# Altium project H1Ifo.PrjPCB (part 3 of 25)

## Sheet IfoPsl.SchDoc: D1800185
size C; Engineer: Daniel Sigg; DocumentNumber: 6; Revision: 4; SheetNumber: 6; SheetTotal: 8
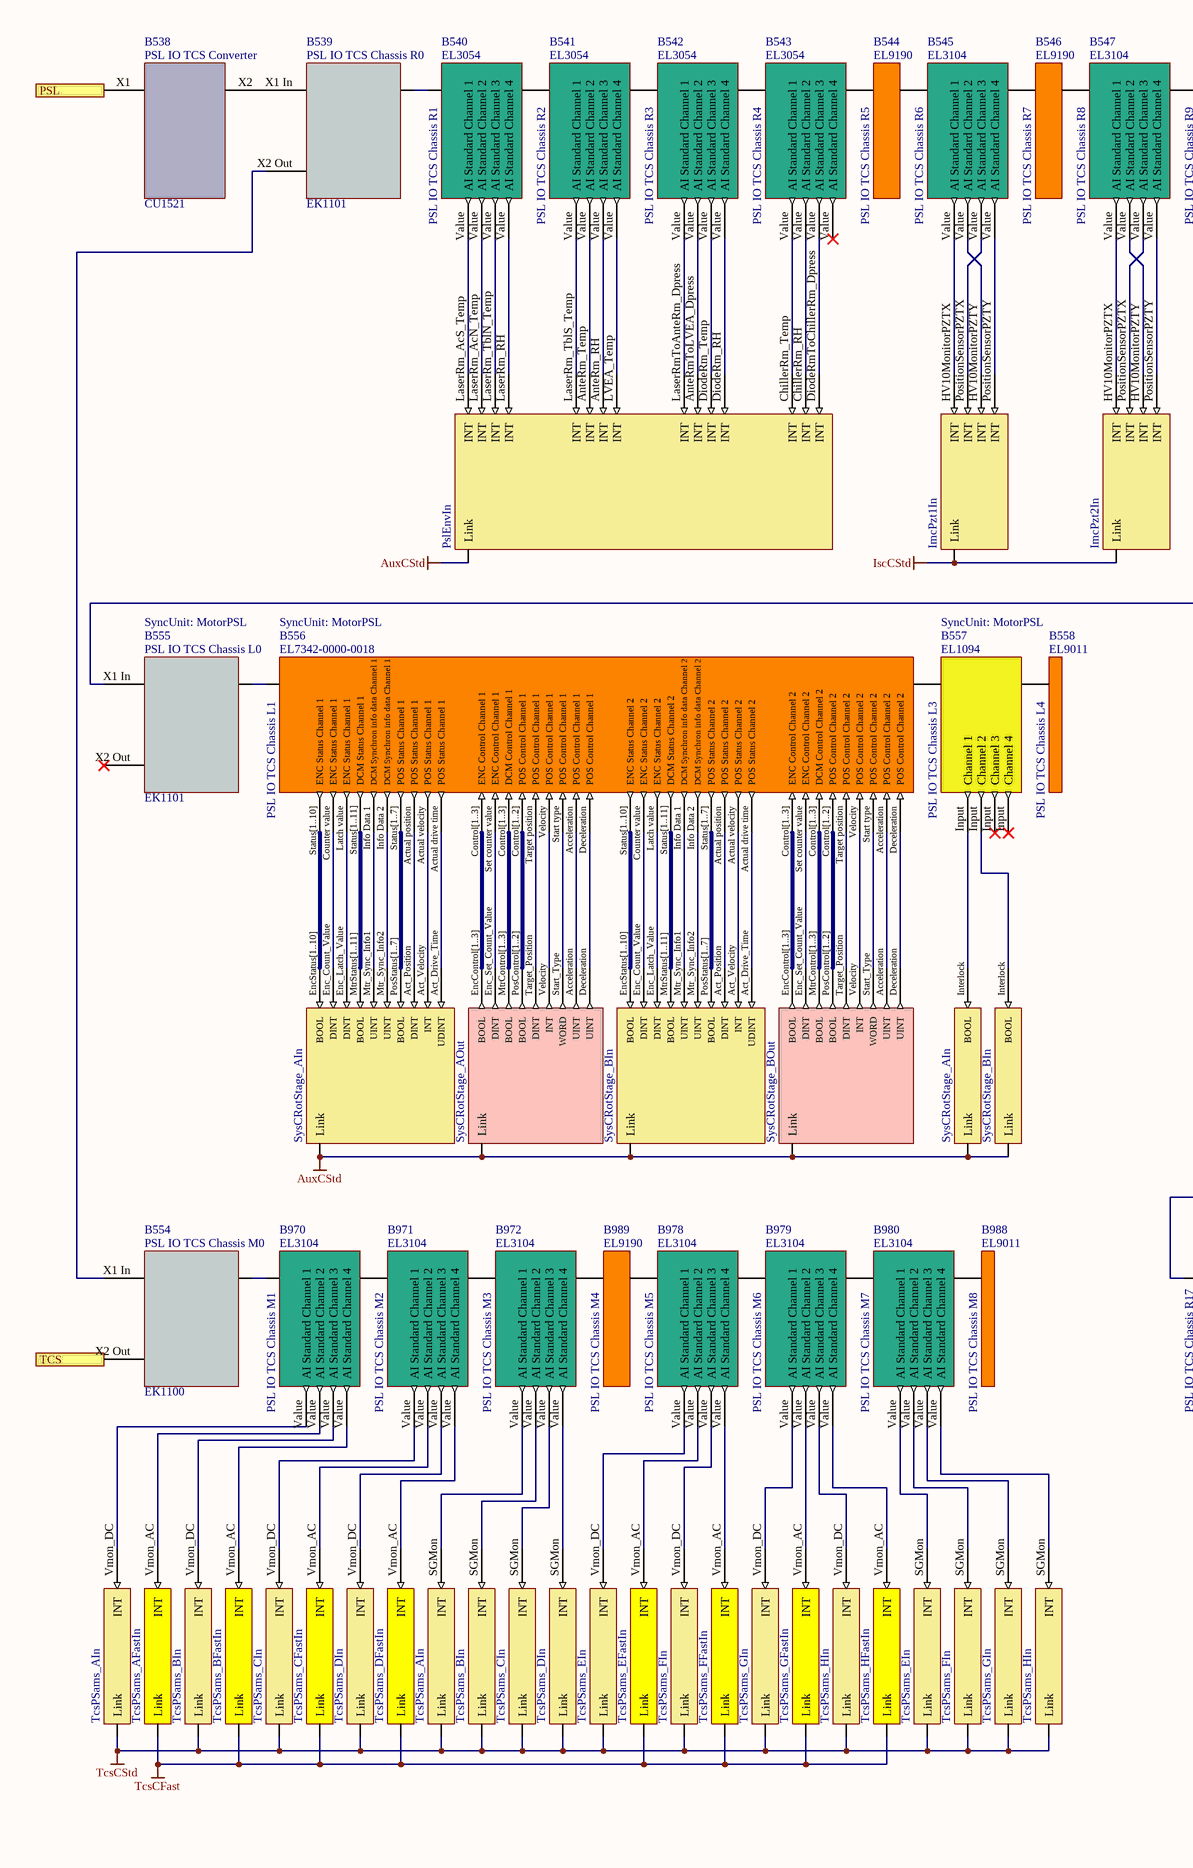
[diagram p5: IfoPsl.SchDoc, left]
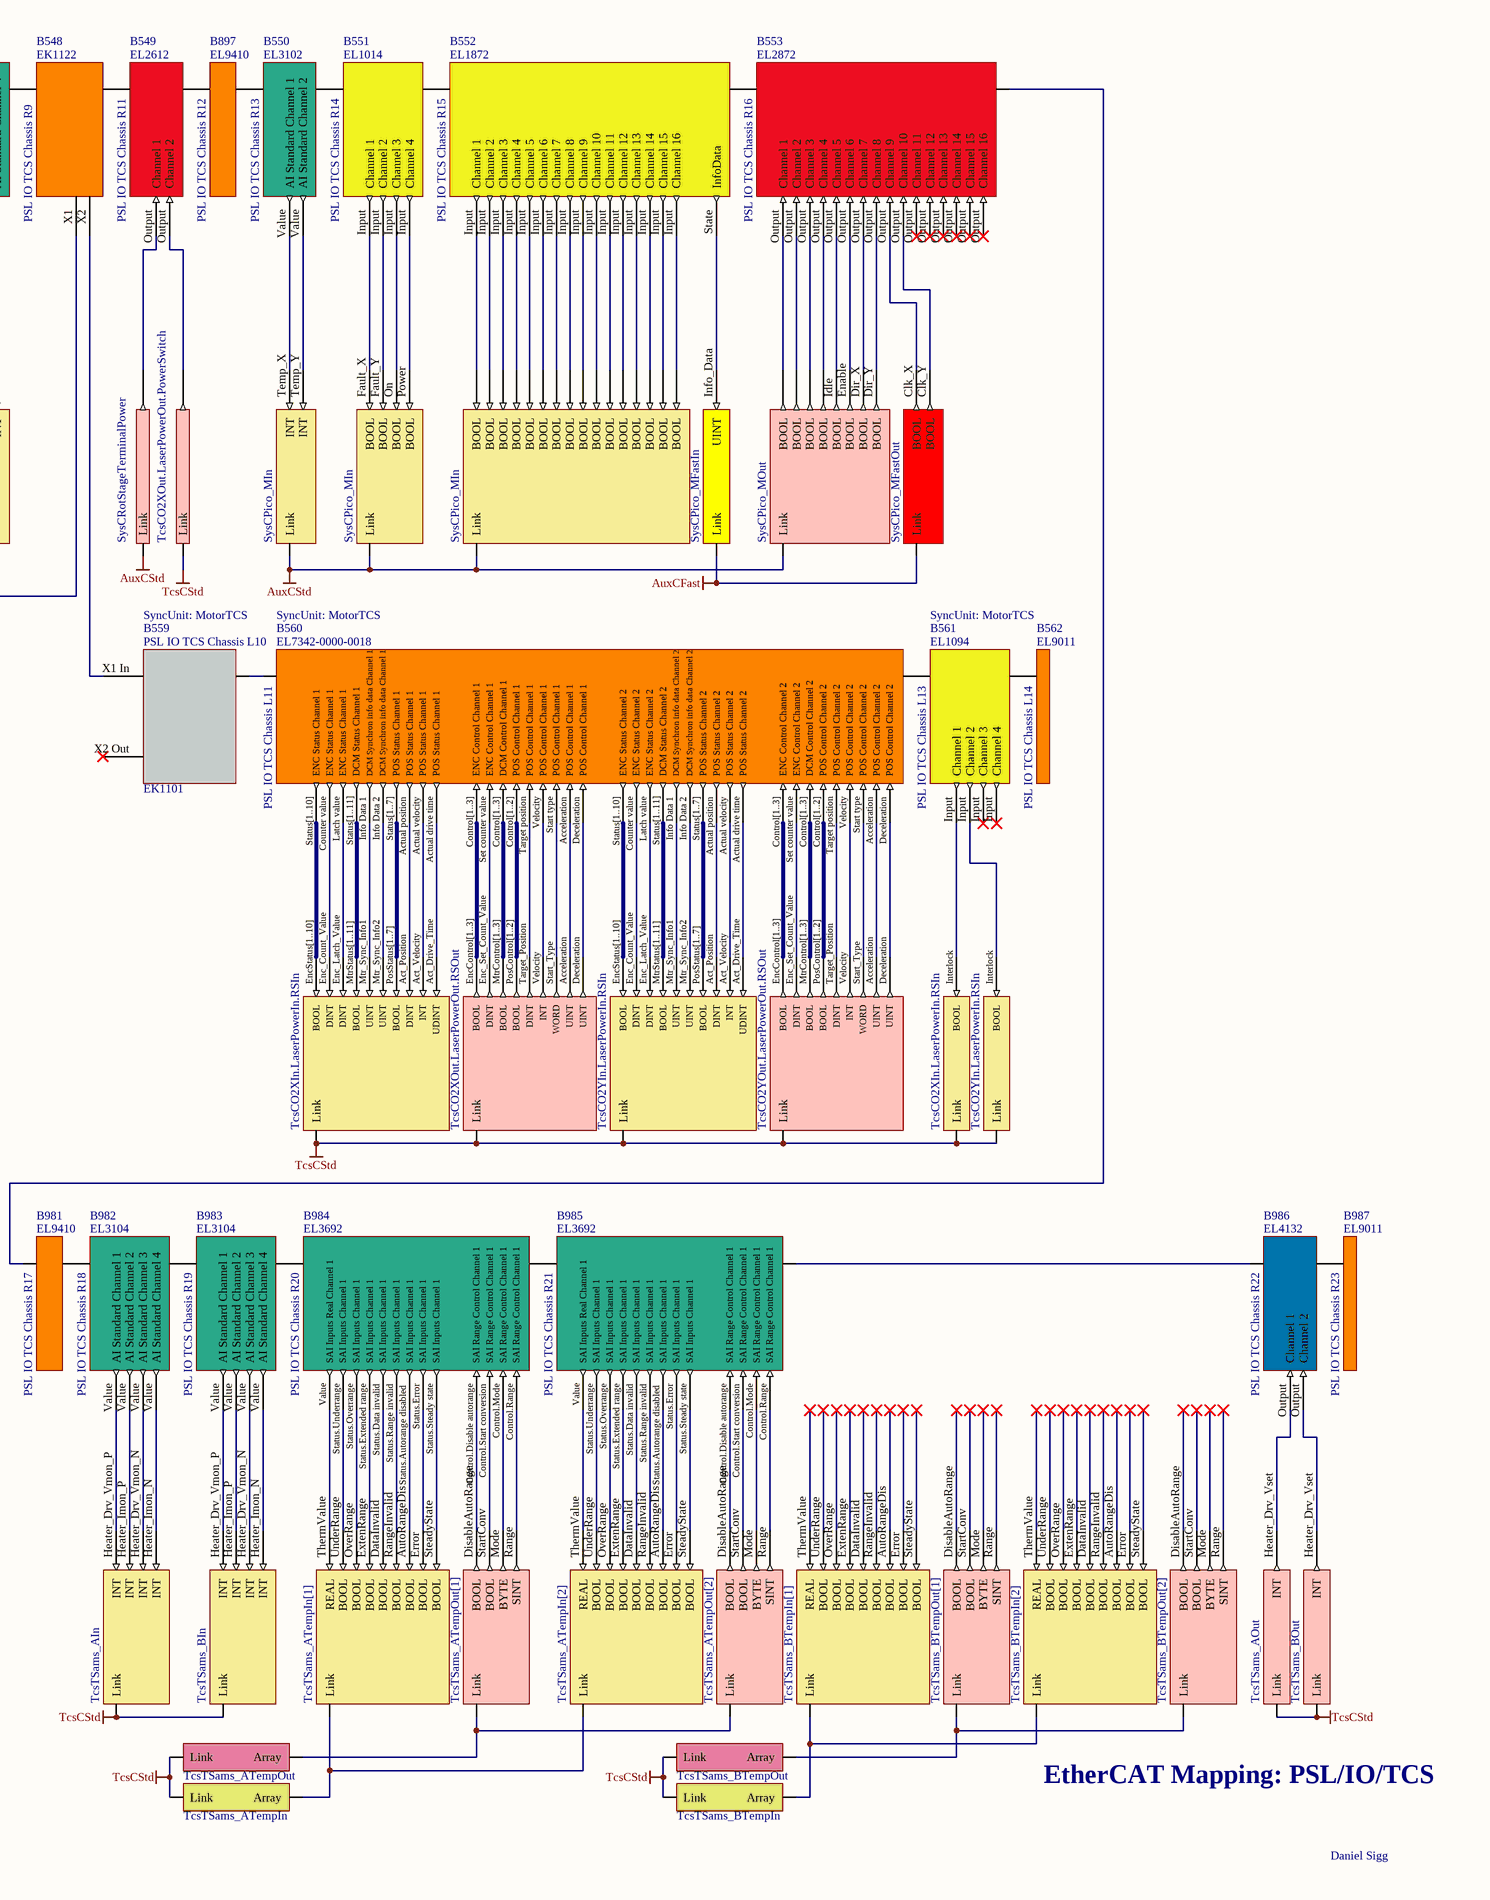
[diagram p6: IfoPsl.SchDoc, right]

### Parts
(Parts that share a designator on the sheet are numbered #1, #2 ... from top to bottom, then left to right.)
B538  PSL IO TCS Converter  Part Number: CU1521  (mechanical)
B539  PSL IO TCS Chassis R0  Part Number: EK1101  (mechanical)
B540  PSL IO TCS Chassis R1  Part Number: EL3054  (mechanical)
B541  PSL IO TCS Chassis R2  Part Number: EL3054  (mechanical)
B542  PSL IO TCS Chassis R3  Part Number: EL3054  (mechanical)
B543  PSL IO TCS Chassis R4  Part Number: EL3054  (mechanical)
B544  PSL IO TCS Chassis R5  Part Number: EL9190  (mechanical)
B545  PSL IO TCS Chassis R6  Part Number: EL3104  (mechanical)
B546  PSL IO TCS Chassis R7  Part Number: EL9190  (mechanical)
B547  PSL IO TCS Chassis R8  Part Number: EL3104  (mechanical)
B548  PSL IO TCS Chassis R9  Part Number: EK1122  (mechanical)
B549  PSL IO TCS Chassis R11  Part Number: EL2612  (mechanical)
B550  PSL IO TCS Chassis R13  Part Number: EL3102  (mechanical)
B551  PSL IO TCS Chassis R14  Part Number: EL1014  (mechanical)
B552  PSL IO TCS Chassis R15  Part Number: EL1872  (mechanical)
B553  PSL IO TCS Chassis R16  Part Number: EL2872  (mechanical)
B554  PSL IO TCS Chassis M0  Part Number: EK1100
B555  PSL IO TCS Chassis L0  Part Number: EK1101  SyncUnit: MotorPSL  (mechanical)
B556  PSL IO TCS Chassis L1  SyncUnit: MotorPSL  Part Number: EL7342-0000-0018  (mechanical)
B557  PSL IO TCS Chassis L3  Part Number: EL1094  SyncUnit: MotorPSL  (mechanical)
B558  PSL IO TCS Chassis L4  Part Number: EL9011  (mechanical)
B559  PSL IO TCS Chassis L10  Part Number: EK1101  SyncUnit: MotorTCS
B560  PSL IO TCS Chassis L11  SyncUnit: MotorTCS  Part Number: EL7342-0000-0018  (mechanical)
B561  PSL IO TCS Chassis L13  Part Number: EL1094  SyncUnit: MotorTCS  (mechanical)
B562  PSL IO TCS Chassis L14  Part Number: EL9011  (mechanical)
B897#1  PSL IO TCS Chassis R12  Part Number: EL9410  (mechanical)
B970  PSL IO TCS Chassis M1  Part Number: EL3104  (mechanical)
B971  PSL IO TCS Chassis M2  Part Number: EL3104  (mechanical)
B972  PSL IO TCS Chassis M3  Part Number: EL3104  (mechanical)
B978  PSL IO TCS Chassis M5  Part Number: EL3104  (mechanical)
B979  PSL IO TCS Chassis M6  Part Number: EL3104  (mechanical)
B980  PSL IO TCS Chassis M7  Part Number: EL3104  (mechanical)
B981  PSL IO TCS Chassis R17  Part Number: EL9410  (mechanical)
B982  PSL IO TCS Chassis R18  Part Number: EL3104  (mechanical)
B983  PSL IO TCS Chassis R19  Part Number: EL3104  (mechanical)
B984  PSL IO TCS Chassis R20  Part Number: EL3692  (mechanical)
B985  PSL IO TCS Chassis R21  Part Number: EL3692  (mechanical)
B986  PSL IO TCS Chassis R22  Part Number: EL4132  (mechanical)
B987  PSL IO TCS Chassis R23  Part Number: EL9011  (mechanical)
B988  PSL IO TCS Chassis M8  Part Number: EL9011  (mechanical)
B989  PSL IO TCS Chassis M4  Part Number: EL9190  (mechanical)
V423  SysCRotStage_AIn  (parts A,B of 2)  (no BOM)
V425  TcsCO2XIn.LaserPowerIn.RSIn  (parts A,B of 2)  (no BOM)
V427  TcsCO2YIn.LaserPowerIn.RSIn  (parts A,B of 2)  (no BOM)
V508  PslEnvIn  (no BOM)
V509  ImcPzt1In  (no BOM)
V510  ImcPzt2In  (no BOM)
V511  SysCRotStageTerminalPower  (no BOM)
V512  TcsCO2XOut.LaserPowerOut.PowerSwitch  (no BOM)
V513  SysCPico_MFastIn  (no BOM)
V514  SysCPico_MOut  (no BOM)
V515  SysCPico_MFastOut  (no BOM)
V516  SysCRotStage_AOut  (no BOM)
V517  TcsCO2XOut.LaserPowerOut.RSOut  (no BOM)
V518  TcsCO2YOut.LaserPowerOut.RSOut  (no BOM)
V699  SysCPico_MIn  (parts A,B,C of 3)  (no BOM)
V801  SysCRotStage_BIn  (parts A,B of 2)  (no BOM)
V802  SysCRotStage_BOut  (no BOM)
V803  TcsTSams_ATempIn[1]  (no BOM)
V804  TcsTSams_ATempOut[1]  (no BOM)
V805  TcsTSams_ATempIn[2]  (no BOM)
V806  TcsTSams_ATempOut[2]  (no BOM)
V807  TcsTSams_BTempIn[1]  (no BOM)
V808  TcsTSams_BTempOut[1]  (no BOM)
V809  TcsTSams_BTempIn[2]  (no BOM)
V810  TcsTSams_BTempOut[2]  (no BOM)
V811  TcsTSams_ATempOut  (no BOM)
V812  TcsTSams_BTempOut  (no BOM)
V813  TcsTSams_ATempIn  (no BOM)
V814  TcsTSams_BTempIn  (no BOM)
V815  TcsTSams_AIn  (no BOM)
V816  TcsTSams_BIn  (no BOM)
V817  TcsTSams_AOut  (no BOM)
V818  TcsTSams_BOut  (no BOM)
V819  TcsPSams_AIn  (parts A,B of 2)  (no BOM)
V820  TcsPSams_AFastIn  (no BOM)
V821  TcsPSams_BIn  (parts A,B of 2)  (no BOM)
V822  TcsPSams_BFastIn  (no BOM)
V823  TcsPSams_CIn  (parts A,B of 2)  (no BOM)
V824  TcsPSams_CFastIn  (no BOM)
V825  TcsPSams_DIn  (parts A,B of 2)  (no BOM)
V826  TcsPSams_DFastIn  (no BOM)
V831  TcsPSams_EIn  (parts A,B of 2)  (no BOM)
V832  TcsPSams_EFastIn  (no BOM)
V833  TcsPSams_FIn  (parts A,B of 2)  (no BOM)
V834  TcsPSams_FFastIn  (no BOM)
V835  TcsPSams_GIn  (parts A,B of 2)  (no BOM)
V836  TcsPSams_GFastIn  (no BOM)
V837  TcsPSams_HIn  (parts A,B of 2)  (no BOM)
V838  TcsPSams_HFastIn  (no BOM)

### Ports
PSL, TCS

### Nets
AuxCFast: V513.0(Link) V515.0(Link)
AuxCStd: V423.0(Link) V423.1(Link) V508.0(Link) V511.?2(Link) V514.0(Link) V516.0(Link) V699.0(Link) V699.1(Link) V699.2(Link) V801.0(Link) V801.1(Link) V802.0(Link)
IscCStd: V509.0(Link) V510.0(Link)
TcsCFast: V820.1(Link) V822.1(Link) V824.1(Link) V826.1(Link) V832.1(Link) V834.1(Link) V836.1(Link) V838.1(Link)
TcsCStd: V425.0(Link) V425.1(Link) V427.0(Link) V427.1(Link) V512.?2(Link) V517.0(Link) V518.0(Link) V811.?1(Link) V812.?1(Link) V813.?1(Link) V814.?1(Link) V815.1(Link) V816.1(Link) V817.0(Link) V818.0(Link) V819.1(Link) V819.2(Link) V821.1(Link) V821.2(Link) V823.1(Link) V823.2(Link) V825.1(Link) V825.2(Link) V831.1(Link) V831.2(Link) V833.1(Link) V833.2(Link) V835.1(Link) V835.2(Link) V837.1(Link) V837.2(Link)
NetB538_X1: B538.X1(A) ; port PSL
NetB538_X2: B538.X2(B) B539.X1_In(A)
NetB539_Ebus: B539.Ebus(B) B540.Ebus(A)
NetB539_X2 Out: B539.X2_Out(C) B554.X1_In(A)
NetB540_Ebus: B540.Ebus(B) B541.Ebus(A)
NetB540_Value: B540.Value(AI_Standard_Channel_1) V508.LaserRm_AcS_Temp(INT)
NetB540_Value: B540.Value(AI_Standard_Channel_2) V508.LaserRm_AcN_Temp(INT)  [a separate net that carries the same name]
NetB540_Value: B540.Value(AI_Standard_Channel_3) V508.LaserRm_TblN_Temp(INT)  [a separate net that carries the same name]
NetB540_Value: B540.Value(AI_Standard_Channel_4) V508.LaserRm_RH(INT)  [a separate net that carries the same name]
NetB541_Ebus: B541.Ebus(B) B542.Ebus(A)
NetB541_Value: B541.Value(AI_Standard_Channel_1) V508.LaserRm_TblS_Temp(INT)
NetB541_Value: B541.Value(AI_Standard_Channel_2) V508.AnteRm_Temp(INT)  [a separate net that carries the same name]
NetB541_Value: B541.Value(AI_Standard_Channel_3) V508.AnteRm_RH(INT)  [a separate net that carries the same name]
NetB541_Value: B541.Value(AI_Standard_Channel_4) V508.LVEA_Temp(INT)  [a separate net that carries the same name]
NetB542_Ebus: B542.Ebus(B) B543.Ebus(A)
NetB542_Value: B542.Value(AI_Standard_Channel_1) V508.LaserRmToAnteRm_Dpress(INT)
NetB542_Value: B542.Value(AI_Standard_Channel_2) V508.AnteRmToLVEA_Dpress(INT)  [a separate net that carries the same name]
NetB542_Value: B542.Value(AI_Standard_Channel_3) V508.DiodeRm_Temp(INT)  [a separate net that carries the same name]
NetB542_Value: B542.Value(AI_Standard_Channel_4) V508.DiodeRm_RH(INT)  [a separate net that carries the same name]
NetB543_Ebus: B543.Ebus(B) B544.Ebus(A)
NetB543_Value: B543.Value(AI_Standard_Channel_1) V508.ChillerRm_Temp(INT)
NetB543_Value: B543.Value(AI_Standard_Channel_2) V508.ChillerRm_RH(INT)  [a separate net that carries the same name]
NetB543_Value: B543.Value(AI_Standard_Channel_3) V508.DiodeRmToChillerRm_Dpress(INT)  [a separate net that carries the same name]
NetB544_Ebus: B544.Ebus(B) B545.Ebus(A)
NetB545_Ebus: B545.Ebus(B) B546.Ebus(A)
NetB545_Value: B545.Value(AI_Standard_Channel_1) V509.HV10MonitorPZTX(INT)
NetB545_Value: B545.Value(AI_Standard_Channel_2) V509.HV10MonitorPZTY(INT)  [a separate net that carries the same name]
NetB545_Value: B545.Value(AI_Standard_Channel_3) V509.PositionSensorPZTX(INT)  [a separate net that carries the same name]
NetB545_Value: B545.Value(AI_Standard_Channel_4) V509.PositionSensorPZTY(INT)  [a separate net that carries the same name]
NetB546_Ebus: B546.Ebus(B) B547.Ebus(A)
NetB547_Ebus: B547.Ebus(B) B548.Ebus(A)
NetB547_Value: B547.Value(AI_Standard_Channel_1) V510.HV10MonitorPZTX(INT)
NetB547_Value: B547.Value(AI_Standard_Channel_2) V510.HV10MonitorPZTY(INT)  [a separate net that carries the same name]
NetB547_Value: B547.Value(AI_Standard_Channel_3) V510.PositionSensorPZTX(INT)  [a separate net that carries the same name]
NetB547_Value: B547.Value(AI_Standard_Channel_4) V510.PositionSensorPZTY(INT)  [a separate net that carries the same name]
NetB548_Ebus: B548.Ebus(C) B549.Ebus(A)
NetB548_X1: B548.X1(D) B555.X1_In(A)
NetB548_X2: B548.X2(B) B559.X1_In(A)
NetB549_Ebus: B549.Ebus(B) B897#1.Ebus(A)
NetB549_Output: B549.Output(Channel_1) V511.?1
NetB549_Output: B549.Output(Channel_2) V512.?1  [a separate net that carries the same name]
NetB550_Ebus: B550.Ebus(B) B551.Ebus(A)
NetB550_Ebus: B550.Ebus(A) B897#1.Ebus(B)  [a separate net that carries the same name]
NetB550_Value: B550.Value(AI_Standard_Channel_1) V699.Temp_X(INT)
NetB550_Value: B550.Value(AI_Standard_Channel_2) V699.Temp_Y(INT)  [a separate net that carries the same name]
NetB551_Ebus: B551.Ebus(B) B552.Ebus(A)
NetB551_Input: B551.Input(Channel_1) V699.Fault_X(BOOL)
NetB551_Input: B551.Input(Channel_2) V699.Fault_Y(BOOL)  [a separate net that carries the same name]
NetB551_Input: B551.Input(Channel_3) V699.On(BOOL)  [a separate net that carries the same name]
NetB551_Input: B551.Input(Channel_4) V699.Power(BOOL)  [a separate net that carries the same name]
NetB552_Ebus: B552.Ebus(B) B553.Ebus(A)
NetB552_Input: B552.Input(Channel_1) V699.MotorX1(BOOL)
NetB552_Input: B552.Input(Channel_2) V699.MotorX2(BOOL)  [a separate net that carries the same name]
NetB552_Input: B552.Input(Channel_3) V699.MotorX3(BOOL)  [a separate net that carries the same name]
NetB552_Input: B552.Input(Channel_4) V699.MotorX4(BOOL)  [a separate net that carries the same name]
NetB552_Input: B552.Input(Channel_5) V699.MotorX5(BOOL)  [a separate net that carries the same name]
NetB552_Input: B552.Input(Channel_6) V699.MotorX6(BOOL)  [a separate net that carries the same name]
NetB552_Input: B552.Input(Channel_7) V699.MotorX7(BOOL)  [a separate net that carries the same name]
NetB552_Input: B552.Input(Channel_8) V699.MotorX8(BOOL)  [a separate net that carries the same name]
NetB552_Input: B552.Input(Channel_9) V699.MotorY1(BOOL)  [a separate net that carries the same name]
NetB552_Input: B552.Input(Channel_10) V699.MotorY2(BOOL)  [a separate net that carries the same name]
NetB552_Input: B552.Input(Channel_11) V699.MotorY3(BOOL)  [a separate net that carries the same name]
NetB552_Input: B552.Input(Channel_12) V699.MotorY4(BOOL)  [a separate net that carries the same name]
NetB552_Input: B552.Input(Channel_13) V699.MotorY5(BOOL)  [a separate net that carries the same name]
NetB552_Input: B552.Input(Channel_14) V699.MotorY6(BOOL)  [a separate net that carries the same name]
NetB552_Input: B552.Input(Channel_15) V699.MotorY7(BOOL)  [a separate net that carries the same name]
NetB552_Input: B552.Input(Channel_16) V699.MotorY8(BOOL)  [a separate net that carries the same name]
NetB552_State: B552.State(InfoData) V513.Info_Data(UINT)
NetB553_Ebus: B553.Ebus(B) B981.Ebus(A)
NetB553_Output: B553.Output(Channel_1) V514.MOTOR3(BOOL)
NetB553_Output: B553.Output(Channel_2) V514.MOTOR2(BOOL)  [a separate net that carries the same name]
NetB553_Output: B553.Output(Channel_3) V514.MOTOR1(BOOL)  [a separate net that carries the same name]
NetB553_Output: B553.Output(Channel_4) V514.MOTOR4(BOOL)  [a separate net that carries the same name]
NetB553_Output: B553.Output(Channel_5) V514.Idle(BOOL)  [a separate net that carries the same name]
NetB553_Output: B553.Output(Channel_6) V514.Enable(BOOL)  [a separate net that carries the same name]
NetB553_Output: B553.Output(Channel_7) V514.Dir_X(BOOL)  [a separate net that carries the same name]
NetB553_Output: B553.Output(Channel_8) V514.Dir_Y(BOOL)  [a separate net that carries the same name]
NetB553_Output: B553.Output(Channel_9) V515.Clk_X(BOOL)  [a separate net that carries the same name]
NetB553_Output: B553.Output(Channel_10) V515.Clk_Y(BOOL)  [a separate net that carries the same name]
NetB554_Ebus: B554.Ebus(B) B970.Ebus(A)
NetB554_X2 Out: B554.X2_Out(C) ; port TCS
NetB555_Ebus: B555.Ebus(B) B556.Ebus(A)
NetB556_Acceleration: B556.Acceleration(POS_Control_Channel_1) V516.Acceleration(UINT)
NetB556_Acceleration: B556.Acceleration(POS_Control_Channel_2) V802.Acceleration(UINT)  [a separate net that carries the same name]
NetB556_Actual drive time: B556.Actual_drive_time(POS_Status_Channel_1) V423.Act_Drive_Time(UDINT)
NetB556_Actual drive time: B556.Actual_drive_time(POS_Status_Channel_2) V801.Act_Drive_Time(UDINT)  [a separate net that carries the same name]
NetB556_Actual position: B556.Actual_position(POS_Status_Channel_1) V423.Act_Position(DINT)
NetB556_Actual position: B556.Actual_position(POS_Status_Channel_2) V801.Act_Position(DINT)  [a separate net that carries the same name]
NetB556_Actual velocity: B556.Actual_velocity(POS_Status_Channel_1) V423.Act_Velocity(INT)
NetB556_Actual velocity: B556.Actual_velocity(POS_Status_Channel_2) V801.Act_Velocity(INT)  [a separate net that carries the same name]
NetB556_Control[1..2]: B556.Control[1..2](POS_Control_Channel_1) V516.PosControl[1..2](BOOL)
NetB556_Control[1..2]: B556.Control[1..2](POS_Control_Channel_2) V802.PosControl[1..2](BOOL)  [a separate net that carries the same name]
NetB556_Control[1..3]: B556.Control[1..3](ENC_Control_Channel_1) V516.EncControl[1..3](BOOL)
NetB556_Control[1..3]: B556.Control[1..3](DCM_Control_Channel_1) V516.MtrControl[1..3](BOOL)  [a separate net that carries the same name]
NetB556_Control[1..3]: B556.Control[1..3](ENC_Control_Channel_2) V802.EncControl[1..3](BOOL)  [a separate net that carries the same name]
NetB556_Control[1..3]: B556.Control[1..3](DCM_Control_Channel_2) V802.MtrControl[1..3](BOOL)  [a separate net that carries the same name]
NetB556_Counter value: B556.Counter_value(ENC_Status_Channel_1) V423.Enc_Count_Value(DINT)
NetB556_Counter value: B556.Counter_value(ENC_Status_Channel_2) V801.Enc_Count_Value(DINT)  [a separate net that carries the same name]
NetB556_Deceleration: B556.Deceleration(POS_Control_Channel_1) V516.Deceleration(UINT)
NetB556_Deceleration: B556.Deceleration(POS_Control_Channel_2) V802.Deceleration(UINT)  [a separate net that carries the same name]
NetB556_Ebus: B556.Ebus(B) B557.Ebus(A)
NetB556_Info Data 1: B556.Info_Data_1(DCM_Synchron_info_data_Channel_1) V423.Mtr_Sync_Info1(UINT)
NetB556_Info Data 1: B556.Info_Data_1(DCM_Synchron_info_data_Channel_2) V801.Mtr_Sync_Info1(UINT)  [a separate net that carries the same name]
NetB556_Info Data 2: B556.Info_Data_2(DCM_Synchron_info_data_Channel_1) V423.Mtr_Sync_Info2(UINT)
NetB556_Info Data 2: B556.Info_Data_2(DCM_Synchron_info_data_Channel_2) V801.Mtr_Sync_Info2(UINT)  [a separate net that carries the same name]
NetB556_Latch value: B556.Latch_value(ENC_Status_Channel_1) V423.Enc_Latch_Value(DINT)
NetB556_Latch value: B556.Latch_value(ENC_Status_Channel_2) V801.Enc_Latch_Value(DINT)  [a separate net that carries the same name]
NetB556_Set counter value: B556.Set_counter_value(ENC_Control_Channel_1) V516.Enc_Set_Count_Value(DINT)
NetB556_Set counter value: B556.Set_counter_value(ENC_Control_Channel_2) V802.Enc_Set_Count_Value(DINT)  [a separate net that carries the same name]
NetB556_Start type: B556.Start_type(POS_Control_Channel_1) V516.Start_Type(WORD)
NetB556_Start type: B556.Start_type(POS_Control_Channel_2) V802.Start_Type(WORD)  [a separate net that carries the same name]
NetB556_Status[1..7]: B556.Status[1..7](POS_Status_Channel_1) V423.PosStatus[1..7](BOOL)
NetB556_Status[1..7]: B556.Status[1..7](POS_Status_Channel_2) V801.PosStatus[1..7](BOOL)  [a separate net that carries the same name]
NetB556_Status[1..10]: B556.Status[1..10](ENC_Status_Channel_1) V423.EncStatus[1..10](BOOL)
NetB556_Status[1..10]: B556.Status[1..10](ENC_Status_Channel_2) V801.EncStatus[1..10](BOOL)  [a separate net that carries the same name]
NetB556_Status[1..11]: B556.Status[1..11](DCM_Status_Channel_1) V423.MtrStatus[1..11](BOOL)
NetB556_Status[1..11]: B556.Status[1..11](DCM_Status_Channel_2) V801.MtrStatus[1..11](BOOL)  [a separate net that carries the same name]
NetB556_Target position: B556.Target_position(POS_Control_Channel_1) V516.Target_Position(DINT)
NetB556_Target position: B556.Target_position(POS_Control_Channel_2) V802.Target_Position(DINT)  [a separate net that carries the same name]
NetB556_Velocity: B556.Velocity(POS_Control_Channel_1) V516.Velocity(INT)
NetB556_Velocity: B556.Velocity(POS_Control_Channel_2) V802.Velocity(INT)  [a separate net that carries the same name]
NetB557_Ebus: B557.Ebus(B) B558.Ebus(A)
NetB557_Input: B557.Input(Channel_1) V423.Interlock(BOOL)
NetB557_Input: B557.Input(Channel_2) V801.Interlock(BOOL)  [a separate net that carries the same name]
NetB559_Ebus: B559.Ebus(B) B560.Ebus(A)
NetB560_Acceleration: B560.Acceleration(POS_Control_Channel_1) V517.Acceleration(UINT)
NetB560_Acceleration: B560.Acceleration(POS_Control_Channel_2) V518.Acceleration(UINT)  [a separate net that carries the same name]
NetB560_Actual drive time: B560.Actual_drive_time(POS_Status_Channel_1) V425.Act_Drive_Time(UDINT)
NetB560_Actual drive time: B560.Actual_drive_time(POS_Status_Channel_2) V427.Act_Drive_Time(UDINT)  [a separate net that carries the same name]
NetB560_Actual position: B560.Actual_position(POS_Status_Channel_1) V425.Act_Position(DINT)
NetB560_Actual position: B560.Actual_position(POS_Status_Channel_2) V427.Act_Position(DINT)  [a separate net that carries the same name]
NetB560_Actual velocity: B560.Actual_velocity(POS_Status_Channel_1) V425.Act_Velocity(INT)
NetB560_Actual velocity: B560.Actual_velocity(POS_Status_Channel_2) V427.Act_Velocity(INT)  [a separate net that carries the same name]
NetB560_Control[1..2]: B560.Control[1..2](POS_Control_Channel_1) V517.PosControl[1..2](BOOL)
NetB560_Control[1..2]: B560.Control[1..2](POS_Control_Channel_2) V518.PosControl[1..2](BOOL)  [a separate net that carries the same name]
NetB560_Control[1..3]: B560.Control[1..3](ENC_Control_Channel_1) V517.EncControl[1..3](BOOL)
NetB560_Control[1..3]: B560.Control[1..3](DCM_Control_Channel_1) V517.MtrControl[1..3](BOOL)  [a separate net that carries the same name]
NetB560_Control[1..3]: B560.Control[1..3](ENC_Control_Channel_2) V518.EncControl[1..3](BOOL)  [a separate net that carries the same name]
NetB560_Control[1..3]: B560.Control[1..3](DCM_Control_Channel_2) V518.MtrControl[1..3](BOOL)  [a separate net that carries the same name]
NetB560_Counter value: B560.Counter_value(ENC_Status_Channel_1) V425.Enc_Count_Value(DINT)
NetB560_Counter value: B560.Counter_value(ENC_Status_Channel_2) V427.Enc_Count_Value(DINT)  [a separate net that carries the same name]
NetB560_Deceleration: B560.Deceleration(POS_Control_Channel_1) V517.Deceleration(UINT)
NetB560_Deceleration: B560.Deceleration(POS_Control_Channel_2) V518.Deceleration(UINT)  [a separate net that carries the same name]
NetB560_Ebus: B560.Ebus(B) B561.Ebus(A)
NetB560_Info Data 1: B560.Info_Data_1(DCM_Synchron_info_data_Channel_1) V425.Mtr_Sync_Info1(UINT)
NetB560_Info Data 1: B560.Info_Data_1(DCM_Synchron_info_data_Channel_2) V427.Mtr_Sync_Info1(UINT)  [a separate net that carries the same name]
NetB560_Info Data 2: B560.Info_Data_2(DCM_Synchron_info_data_Channel_1) V425.Mtr_Sync_Info2(UINT)
NetB560_Info Data 2: B560.Info_Data_2(DCM_Synchron_info_data_Channel_2) V427.Mtr_Sync_Info2(UINT)  [a separate net that carries the same name]
NetB560_Latch value: B560.Latch_value(ENC_Status_Channel_1) V425.Enc_Latch_Value(DINT)
NetB560_Latch value: B560.Latch_value(ENC_Status_Channel_2) V427.Enc_Latch_Value(DINT)  [a separate net that carries the same name]
NetB560_Set counter value: B560.Set_counter_value(ENC_Control_Channel_1) V517.Enc_Set_Count_Value(DINT)
NetB560_Set counter value: B560.Set_counter_value(ENC_Control_Channel_2) V518.Enc_Set_Count_Value(DINT)  [a separate net that carries the same name]
NetB560_Start type: B560.Start_type(POS_Control_Channel_1) V517.Start_Type(WORD)
NetB560_Start type: B560.Start_type(POS_Control_Channel_2) V518.Start_Type(WORD)  [a separate net that carries the same name]
NetB560_Status[1..7]: B560.Status[1..7](POS_Status_Channel_1) V425.PosStatus[1..7](BOOL)
NetB560_Status[1..7]: B560.Status[1..7](POS_Status_Channel_2) V427.PosStatus[1..7](BOOL)  [a separate net that carries the same name]
NetB560_Status[1..10]: B560.Status[1..10](ENC_Status_Channel_1) V425.EncStatus[1..10](BOOL)
NetB560_Status[1..10]: B560.Status[1..10](ENC_Status_Channel_2) V427.EncStatus[1..10](BOOL)  [a separate net that carries the same name]
NetB560_Status[1..11]: B560.Status[1..11](DCM_Status_Channel_1) V425.MtrStatus[1..11](BOOL)
NetB560_Status[1..11]: B560.Status[1..11](DCM_Status_Channel_2) V427.MtrStatus[1..11](BOOL)  [a separate net that carries the same name]
NetB560_Target position: B560.Target_position(POS_Control_Channel_1) V517.Target_Position(DINT)
NetB560_Target position: B560.Target_position(POS_Control_Channel_2) V518.Target_Position(DINT)  [a separate net that carries the same name]
NetB560_Velocity: B560.Velocity(POS_Control_Channel_1) V517.Velocity(INT)
NetB560_Velocity: B560.Velocity(POS_Control_Channel_2) V518.Velocity(INT)  [a separate net that carries the same name]
NetB561_Ebus: B561.Ebus(B) B562.Ebus(A)
NetB561_Input: B561.Input(Channel_1) V425.Interlock(BOOL)
NetB561_Input: B561.Input(Channel_2) V427.Interlock(BOOL)  [a separate net that carries the same name]
NetB970_Ebus: B970.Ebus(B) B971.Ebus(A)
NetB970_Value: B970.Value(AI_Standard_Channel_1) V819.Vmon_DC(INT)
NetB970_Value: B970.Value(AI_Standard_Channel_2) V820.Vmon_AC(INT)  [a separate net that carries the same name]
NetB970_Value: B970.Value(AI_Standard_Channel_3) V821.Vmon_DC(INT)  [a separate net that carries the same name]
NetB970_Value: B970.Value(AI_Standard_Channel_4) V822.Vmon_AC(INT)  [a separate net that carries the same name]
NetB971_Ebus: B971.Ebus(B) B972.Ebus(A)
NetB971_Value: B971.Value(AI_Standard_Channel_1) V823.Vmon_DC(INT)
NetB971_Value: B971.Value(AI_Standard_Channel_2) V824.Vmon_AC(INT)  [a separate net that carries the same name]
NetB971_Value: B971.Value(AI_Standard_Channel_3) V825.Vmon_DC(INT)  [a separate net that carries the same name]
NetB971_Value: B971.Value(AI_Standard_Channel_4) V826.Vmon_AC(INT)  [a separate net that carries the same name]
NetB972_Ebus: B972.Ebus(B) B989.Ebus(A)
NetB972_Value: B972.Value(AI_Standard_Channel_1) V819.SGMon(INT)
NetB972_Value: B972.Value(AI_Standard_Channel_2) V821.SGMon(INT)  [a separate net that carries the same name]
NetB972_Value: B972.Value(AI_Standard_Channel_3) V823.SGMon(INT)  [a separate net that carries the same name]
NetB972_Value: B972.Value(AI_Standard_Channel_4) V825.SGMon(INT)  [a separate net that carries the same name]
NetB978_Ebus: B978.Ebus(A) B989.Ebus(B)
NetB978_Ebus: B978.Ebus(B) B979.Ebus(A)  [a separate net that carries the same name]
NetB978_Value: B978.Value(AI_Standard_Channel_1) V831.Vmon_DC(INT)
NetB978_Value: B978.Value(AI_Standard_Channel_2) V832.Vmon_AC(INT)  [a separate net that carries the same name]
NetB978_Value: B978.Value(AI_Standard_Channel_3) V833.Vmon_DC(INT)  [a separate net that carries the same name]
NetB978_Value: B978.Value(AI_Standard_Channel_4) V834.Vmon_AC(INT)  [a separate net that carries the same name]
NetB979_Ebus: B979.Ebus(B) B980.Ebus(A)
NetB979_Value: B979.Value(AI_Standard_Channel_1) V835.Vmon_DC(INT)
NetB979_Value: B979.Value(AI_Standard_Channel_2) V836.Vmon_AC(INT)  [a separate net that carries the same name]
NetB979_Value: B979.Value(AI_Standard_Channel_3) V837.Vmon_DC(INT)  [a separate net that carries the same name]
NetB979_Value: B979.Value(AI_Standard_Channel_4) V838.Vmon_AC(INT)  [a separate net that carries the same name]
NetB980_Ebus: B980.Ebus(B) B988.Ebus(A)
NetB980_Value: B980.Value(AI_Standard_Channel_1) V831.SGMon(INT)
NetB980_Value: B980.Value(AI_Standard_Channel_2) V833.SGMon(INT)  [a separate net that carries the same name]
NetB980_Value: B980.Value(AI_Standard_Channel_3) V835.SGMon(INT)  [a separate net that carries the same name]
NetB980_Value: B980.Value(AI_Standard_Channel_4) V837.SGMon(INT)  [a separate net that carries the same name]
NetB981_Ebus: B981.Ebus(B) B982.Ebus(A)
NetB982_Ebus: B982.Ebus(B) B983.Ebus(A)
NetB982_Value: B982.Value(AI_Standard_Channel_1) V815.Heater_Drv_Vmon_P(INT)
NetB982_Value: B982.Value(AI_Standard_Channel_2) V815.Heater_Imon_P(INT)  [a separate net that carries the same name]
NetB982_Value: B982.Value(AI_Standard_Channel_3) V815.Heater_Drv_Vmon_N(INT)  [a separate net that carries the same name]
NetB982_Value: B982.Value(AI_Standard_Channel_4) V815.Heater_Imon_N(INT)  [a separate net that carries the same name]
NetB983_Ebus: B983.Ebus(B) B984.Ebus(A)
NetB983_Value: B983.Value(AI_Standard_Channel_1) V816.Heater_Drv_Vmon_P(INT)
NetB983_Value: B983.Value(AI_Standard_Channel_2) V816.Heater_Imon_P(INT)  [a separate net that carries the same name]
NetB983_Value: B983.Value(AI_Standard_Channel_3) V816.Heater_Drv_Vmon_N(INT)  [a separate net that carries the same name]
NetB983_Value: B983.Value(AI_Standard_Channel_4) V816.Heater_Imon_N(INT)  [a separate net that carries the same name]
NetB984_Control.Disable autorange: B984.Control.Disable_autorange(SAI_Range_Control_Channel_1) V804.DisableAutoRange(BOOL)
NetB984_Control.Mode: B984.Control.Mode(SAI_Range_Control_Channel_1) V804.Mode(BYTE)
NetB984_Control.Range: B984.Control.Range(SAI_Range_Control_Channel_1) V804.Range(SINT)
NetB984_Control.Start conversion: B984.Control.Start_conversion(SAI_Range_Control_Channel_1) V804.StartConv(BOOL)
NetB984_Ebus: B984.Ebus(B) B985.Ebus(A)
NetB984_Status.Autorange disabled: B984.Status.Autorange_disabled(SAI_Inputs_Channel_1) V803.AutoRangeDis(BOOL)
NetB984_Status.Data invalid: B984.Status.Data_invalid(SAI_Inputs_Channel_1) V803.DataInvalid(BOOL)
NetB984_Status.Error: B984.Status.Error(SAI_Inputs_Channel_1) V803.Error(BOOL)
NetB984_Status.Extended range: B984.Status.Extended_range(SAI_Inputs_Channel_1) V803.ExtenRange(BOOL)
NetB984_Status.Overrange: B984.Status.Overrange(SAI_Inputs_Channel_1) V803.OverRange(BOOL)
NetB984_Status.Range invalid: B984.Status.Range_invalid(SAI_Inputs_Channel_1) V803.RangeInvalid(BOOL)
NetB984_Status.Steady state: B984.Status.Steady_state(SAI_Inputs_Channel_1) V803.SteadyState(BOOL)
NetB984_Status.Underrange: B984.Status.Underrange(SAI_Inputs_Channel_1) V803.UnderRange(BOOL)
NetB984_Value: B984.Value(SAI_Inputs_Real_Channel_1) V803.ThermValue(REAL)
NetB985_Control.Disable autorange: B985.Control.Disable_autorange(SAI_Range_Control_Channel_1) V806.DisableAutoRange(BOOL)
NetB985_Control.Mode: B985.Control.Mode(SAI_Range_Control_Channel_1) V806.Mode(BYTE)
NetB985_Control.Range: B985.Control.Range(SAI_Range_Control_Channel_1) V806.Range(SINT)
NetB985_Control.Start conversion: B985.Control.Start_conversion(SAI_Range_Control_Channel_1) V806.StartConv(BOOL)
NetB985_Ebus: B985.Ebus(B) B986.Ebus(A)
NetB985_Status.Autorange disabled: B985.Status.Autorange_disabled(SAI_Inputs_Channel_1) V805.AutoRangeDis(BOOL)
NetB985_Status.Data invalid: B985.Status.Data_invalid(SAI_Inputs_Channel_1) V805.DataInvalid(BOOL)
NetB985_Status.Error: B985.Status.Error(SAI_Inputs_Channel_1) V805.Error(BOOL)
NetB985_Status.Extended range: B985.Status.Extended_range(SAI_Inputs_Channel_1) V805.ExtenRange(BOOL)
NetB985_Status.Overrange: B985.Status.Overrange(SAI_Inputs_Channel_1) V805.OverRange(BOOL)
NetB985_Status.Range invalid: B985.Status.Range_invalid(SAI_Inputs_Channel_1) V805.RangeInvalid(BOOL)
NetB985_Status.Steady state: B985.Status.Steady_state(SAI_Inputs_Channel_1) V805.SteadyState(BOOL)
NetB985_Status.Underrange: B985.Status.Underrange(SAI_Inputs_Channel_1) V805.UnderRange(BOOL)
NetB985_Value: B985.Value(SAI_Inputs_Real_Channel_1) V805.ThermValue(REAL)
NetB986_Ebus: B986.Ebus(B) B987.Ebus(A)
NetB986_Output: B986.Output(Channel_1) V817.Heater_Drv_Vset(INT)
NetB986_Output: B986.Output(Channel_2) V818.Heater_Drv_Vset(INT)  [a separate net that carries the same name]
NetV803_1: V803.1(Link) V805.1(Link) V813.?2(Array)
NetV804_1: V804.1(Link) V806.1(Link) V811.?2(Array)
NetV807_1: V807.1(Link) V809.1(Link) V814.?2(Array)
NetV808_1: V808.1(Link) V810.1(Link) V812.?2(Array)

Not connected (* = marked no-connect by the designer): B555 X2 Out(C)*; B559 X2 Out(C)*; V807 AutoRangeDis(BOOL)* DataInvalid(BOOL)* Error(BOOL)* ExtenRange(BOOL)* OverRange(BOOL)* RangeInvalid(BOOL)* SteadyState(BOOL)* ThermValue(REAL)* UnderRange(BOOL)*; V808 DisableAutoRange(BOOL)* Mode(BYTE)* Range(SINT)* StartConv(BOOL)*; V809 AutoRangeDis(BOOL)* DataInvalid(BOOL)* Error(BOOL)* ExtenRange(BOOL)* OverRange(BOOL)* RangeInvalid(BOOL)* SteadyState(BOOL)* ThermValue(REAL)* UnderRange(BOOL)*; V810 DisableAutoRange(BOOL)* Mode(BYTE)* Range(SINT)* StartConv(BOOL)*

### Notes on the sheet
- EtherCAT Mapping: PSL/IO/TCS
- Daniel Sigg

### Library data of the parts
B538 = MediaConverterFiberToCAT5: EtherCAT Media Converter; BoxType: Box; BoxNextB: TPHEWRKC; BoxPrev: BGADWTKS; PortPrevFull: 1001/B; PortPrevShort: B 'X1'; Fullname: TIID^Vertex PSL TCS (EtherCAT)^PSL IO TCS Converter (CU1521); BoxAddr: 1002; Disabled: False
B539 = CouplerEK1101: EtherCAT Coupler; Rail: Right; BoxNextB: WBQMEEAU; BoxNextC: YQKRVLKQ; BoxPrev: MGVQPUOL; PortPrevFull: 1002/B; PortPrevShort: B 'X2'; Fullname: TIID^Vertex PSL TCS (EtherCAT)^PSL IO TCS Chassis R0 (EK1101); BoxPorts: Junction; BoxAddr: 1003; Disabled: False
B540 = TerminalEL3054: EtherCAT Terminal EL3054 4-channel analog input terminal 4…20 mA, single-ended, 12 bit; Rail: Right; BoxNextB: AXUTBMHX; BoxPrev: TPHEWRKC; PortPrevFull: 1003/B; PortPrevShort: B; Fullname: TIID^Vertex PSL TCS (EtherCAT)^PSL IO TCS Chassis R0 (EK1101)^PSL IO TCS Chassis R1 (EL3054); BoxAddr: 1004; Disabled: False
B541 = TerminalEL3054: EtherCAT Terminal EL3054 4-channel analog input terminal 4…20 mA, single-ended, 12 bit; Rail: Right; BoxNextB: UHOBBQHA; BoxPrev: WBQMEEAU; PortPrevFull: 1004/B; PortPrevShort: B; Fullname: TIID^Vertex PSL TCS (EtherCAT)^PSL IO TCS Chassis R0 (EK1101)^PSL IO TCS Chassis R2 (EL3054); BoxAddr: 1005; Disabled: False
B542 = TerminalEL3054: EtherCAT Terminal EL3054 4-channel analog input terminal 4…20 mA, single-ended, 12 bit; Rail: Right; BoxNextB: MIILOAPU; BoxPrev: AXUTBMHX; PortPrevFull: 1005/B; PortPrevShort: B; Fullname: TIID^Vertex PSL TCS (EtherCAT)^PSL IO TCS Chassis R0 (EK1101)^PSL IO TCS Chassis R3 (EL3054); BoxAddr: 1006; Disabled: False
B543 = TerminalEL3054: EtherCAT Terminal EL3054 4-channel analog input terminal 4…20 mA, single-ended, 12 bit; Rail: Right; BoxNextB: AQOKKGKC; BoxPrev: UHOBBQHA; PortPrevFull: 1006/B; PortPrevShort: B; Fullname: TIID^Vertex PSL TCS (EtherCAT)^PSL IO TCS Chassis R0 (EK1101)^PSL IO TCS Chassis R4 (EL3054); BoxAddr: 1007; Disabled: False
B544 = TerminalEL9190: EtherCAT Terminal EL9190 Supply; BoxType: TerminalPassive; Rail: Right; BoxNextB: JPGIXLJR; BoxPrev: MIILOAPU; PortPrevShort: B; Fullname: TIID^Vertex PSL TCS (EtherCAT)^PSL IO TCS Chassis R0 (EK1101)^PSL IO TCS Chassis R5 (EL9190); Disabled: False
B545 = TerminalEL3104: EtherCAT Terminal EL3104 4-chn Analog Input; Rail: Right; BoxNextB: EYCDPXKQ; BoxPrev: AQOKKGKC; PortPrevFull: 1007/B; PortPrevShort: B; Fullname: TIID^Vertex PSL TCS (EtherCAT)^PSL IO TCS Chassis R0 (EK1101)^PSL IO TCS Chassis R6 (EL3104); BoxAddr: 1008; Disabled: False
B546 = TerminalEL9190: EtherCAT Terminal EL9190 Supply; BoxType: TerminalPassive; Rail: Right; BoxNextB: PVXJNMKY; BoxPrev: JPGIXLJR; PortPrevShort: B; Fullname: TIID^Vertex PSL TCS (EtherCAT)^PSL IO TCS Chassis R0 (EK1101)^PSL IO TCS Chassis R7 (EL9190); Disabled: False
B547 = TerminalEL3104: EtherCAT Terminal EL3104 4-chn Analog Input; Rail: Right; BoxNextB: DUAPLILY; BoxPrev: EYCDPXKQ; PortPrevFull: 1008/B; PortPrevShort: B; Fullname: TIID^Vertex PSL TCS (EtherCAT)^PSL IO TCS Chassis R0 (EK1101)^PSL IO TCS Chassis R8 (EL3104); BoxAddr: 1009; Disabled: False
B548 = TerminalEK1122: EtherCAT Terminal EK1122 ¦ 2-port EtherCAT junction; Rail: Right; BoxNextB: VSWLHQMN; BoxNextC: HXYYNLLI; BoxNextD: GBUNHTNS; BoxPrev: PVXJNMKY; PortPrevFull: 1009/B; PortPrevShort: B; Fullname: TIID^Vertex PSL TCS (EtherCAT)^PSL IO TCS Chassis R0 (EK1101)^PSL IO TCS Chassis R9 (EK1122); BoxAddr: 1010; Disabled: False
B549 = TerminalEL2612: EtherCAT Terminal 2-channel relay output terminal 125 V AC/30 V DC, change-over; Rail: Right; BoxNextB: GINNFXLQ; BoxPrev: DUAPLILY; PortPrevFull: 1010/C; PortPrevShort: C; Fullname: TIID^Vertex PSL TCS (EtherCAT)^PSL IO TCS Chassis R0 (EK1101)^PSL IO TCS Chassis R11 (EL2612); BoxAddr: 1017; Disabled: False
B550 = TerminalEL3102: EtherCAT Terminal EL3102 2-chn Analog Input; Rail: Right; BoxNextB: YOOFXXDD; BoxPrev: GINNFXLQ; PortPrevFull: 1018/B; PortPrevShort: B; Fullname: TIID^Vertex PSL TCS (EtherCAT)^PSL IO TCS Chassis R0 (EK1101)^PSL IO TCS Chassis R13 (EL3102); BoxAddr: 1019; Disabled: False
B551 = TerminalEL1014: EtherCAT Terminal EL1014 4-channel digital input terminal 24 V DC; Rail: Right; BoxNextB: HXZBDTCM; BoxPrev: IMGYVLLL; PortPrevFull: 1019/B; PortPrevShort: B; Fullname: TIID^Vertex PSL TCS (EtherCAT)^PSL IO TCS Chassis R0 (EK1101)^PSL IO TCS Chassis R14 (EL1014); BoxAddr: 1020; Disabled: False
B552 = TerminalEL1872InfoData: EtherCAT Terminal EL1872 16-channel digital input terminal 24 V DC; Rail: Right; BoxNextB: UJFOJQPA; BoxPrev: YOOFXXDD; PortPrevFull: 1020/B; PortPrevShort: B; Fullname: TIID^Vertex PSL TCS (EtherCAT)^PSL IO TCS Chassis R0 (EK1101)^PSL IO TCS Chassis R15 (EL1872); BoxAddr: 1021; Disabled: False
B553 = TerminalEL2872: EtherCAT Terminal EL2872 16-channel digital output terminal 24 V DC; Rail: Right; BoxNextB: FDMBFDOD; BoxPrev: HXZBDTCM; PortPrevFull: 1021/B; PortPrevShort: B; Fullname: TIID^Vertex PSL TCS (EtherCAT)^PSL IO TCS Chassis R0 (EK1101)^PSL IO TCS Chassis R16 (EL2872); BoxAddr: 1022; Disabled: False
B554 = CouplerEK1100: EtherCAT Coupler; Rail: Middle; BoxNextB: FTJGNQXO; BoxNextC: TXISYRED; BoxPrev: TPHEWRKC; PortPrevFull: 1003/C; PortPrevShort: C 'X2 Out'; Fullname: TIID^Vertex PSL TCS (EtherCAT)^PSL IO TCS Chassis M0 (EK1100); BoxPorts: Junction; BoxAddr: 1029; Disabled: False
B555 = CouplerEK1101: EtherCAT Coupler; Rail: Left; BoxNextB: NRTAXIAP; BoxPrev: DUAPLILY; PortPrevFull: 1010/D; PortPrevShort: D 'X1'; Fullname: TIID^Vertex PSL TCS (EtherCAT)^PSL IO TCS Chassis R0 (EK1101)^PSL IO TCS Chassis R9 (EK1122)^PSL IO TCS Chassis L0 (EK1101); BoxPorts: Junction; BoxAddr: 1011; Disabled: False
B556 = TerminalEL7342bus: EtherCAT Terminal EL7342 2-channel DC motor output stage 50 V DC, 3.5 A; Rail: Left; BoxNextB: YCGJATNL; BoxPrev: GBUNHTNS; PortPrevFull: 1011/B; PortPrevShort: B; Fullname: TIID^Vertex PSL TCS (EtherCAT)^PSL IO TCS Chassis R0 (EK1101)^PSL IO TCS Chassis R9 (EK1122)^PSL IO TCS Chassis L0 (EK1101)^PSL IO TCS Chassis L1 (EL7342-0000-0018); BoxAddr: 1012; PDO Outputs: 0x1601,0x1603,0x1604,0x1607,0x160B,0x160D; PDO Inputs: 0x1A01,0x1A04,0x1A06,0x1A07,0x1A08,0x1A09,0x1A0B,0x1A0D; Disabled: False
B557 = TerminalEL1094: EtherCAT Terminal EL1094 4-channel digital input terminal 24 V DC, switching to negative potential; Rail: Left; BoxNextB: DNPLFSLH; BoxPrev: NRTAXIAP; PortPrevFull: 1012/B; PortPrevShort: B; Fullname: TIID^Vertex PSL TCS (EtherCAT)^PSL IO TCS Chassis R0 (EK1101)^PSL IO TCS Chassis R9 (EK1122)^PSL IO TCS Chassis L0 (EK1101)^PSL IO TCS Chassis L3 (EL1094); BoxAddr: 1013; Disabled: False
B558 = TerminalEL9011: EtherCAT Terminal EL9011 End; BoxType: TerminalPassive; Rail: Left; BoxPrev: YCGJATNL; PortPrevShort: B; Fullname: TIID^Vertex PSL TCS (EtherCAT)^PSL IO TCS Chassis R0 (EK1101)^PSL IO TCS Chassis R9 (EK1122)^PSL IO TCS Chassis L0 (EK1101)^PSL IO TCS Chassis L4 (EL9011); Disabled: False
B559 = CouplerEK1101: EtherCAT Coupler; Rail: Left; BoxNextB: RIMSKYEN; BoxPrev: DUAPLILY; PortPrevFull: 1010/B; PortPrevShort: B 'X2'; Fullname: TIID^Vertex PSL TCS (EtherCAT)^PSL IO TCS Chassis R0 (EK1101)^PSL IO TCS Chassis R9 (EK1122)^PSL IO TCS Chassis L10 (EK1101); BoxPorts: Junction; BoxAddr: 1014; Disabled: False
B560 = TerminalEL7342bus: EtherCAT Terminal EL7342 2-channel DC motor output stage 50 V DC, 3.5 A; Rail: Left; BoxNextB: NDHIYFAO; BoxPrev: VSWLHQMN; PortPrevFull: 1014/B; PortPrevShort: B; Fullname: TIID^Vertex PSL TCS (EtherCAT)^PSL IO TCS Chassis R0 (EK1101)^PSL IO TCS Chassis R9 (EK1122)^PSL IO TCS Chassis L10 (EK1101)^PSL IO TCS Chassis L11 (EL7342-0000-0018); BoxAddr: 1015; PDO Outputs: 0x1601,0x1603,0x1604,0x1607,0x160B,0x160D; PDO Inputs: 0x1A01,0x1A04,0x1A06,0x1A07,0x1A08,0x1A09,0x1A0B,0x1A0D; Disabled: False
B561 = TerminalEL1094: EtherCAT Terminal EL1094 4-channel digital input terminal 24 V DC, switching to negative potential; Rail: Left; BoxNextB: SBTYDYBD; BoxPrev: RIMSKYEN; PortPrevFull: 1015/B; PortPrevShort: B; Fullname: TIID^Vertex PSL TCS (EtherCAT)^PSL IO TCS Chassis R0 (EK1101)^PSL IO TCS Chassis R9 (EK1122)^PSL IO TCS Chassis L10 (EK1101)^PSL IO TCS Chassis L13 (EL1094); BoxAddr: 1016; Disabled: False
B562 = TerminalEL9011: EtherCAT Terminal EL9011 End; BoxType: TerminalPassive; Rail: Left; BoxPrev: NDHIYFAO; PortPrevShort: B; Fullname: TIID^Vertex PSL TCS (EtherCAT)^PSL IO TCS Chassis R0 (EK1101)^PSL IO TCS Chassis R9 (EK1122)^PSL IO TCS Chassis L10 (EK1101)^PSL IO TCS Chassis L14 (EL9011); Disabled: False
B897#1 = TerminalEL9410: EtherCAT Terminal EL9410 Power; Rail: Right; BoxNextB: IMGYVLLL; BoxPrev: HXYYNLLI; PortPrevFull: 1017/B; PortPrevShort: B; Fullname: TIID^Vertex PSL TCS (EtherCAT)^PSL IO TCS Chassis R0 (EK1101)^PSL IO TCS Chassis R12 (EL9410); BoxAddr: 1018; Disabled: False
B970 = TerminalEL3104: EtherCAT Terminal EL3104 4-chn Analog Input; Rail: Middle; BoxNextB: VREYJYTA; BoxPrev: YQKRVLKQ; PortPrevFull: 1029/B; PortPrevShort: B; Fullname: TIID^Vertex PSL TCS (EtherCAT)^PSL IO TCS Chassis M0 (EK1100)^PSL IO TCS Chassis M1 (EL3104); BoxAddr: 1030; Disabled: False
B971 = TerminalEL3104: EtherCAT Terminal EL3104 4-chn Analog Input; Rail: Middle; BoxNextB: XAYIQLOT; BoxPrev: FTJGNQXO; PortPrevFull: 1030/B; PortPrevShort: B; Fullname: TIID^Vertex PSL TCS (EtherCAT)^PSL IO TCS Chassis M0 (EK1100)^PSL IO TCS Chassis M2 (EL3104); BoxAddr: 1031; Disabled: False
B972 = TerminalEL3104: EtherCAT Terminal EL3104 4-chn Analog Input; Rail: Middle; BoxNextB: SAGAPHCA; BoxPrev: VREYJYTA; PortPrevFull: 1031/B; PortPrevShort: B; Fullname: TIID^Vertex PSL TCS (EtherCAT)^PSL IO TCS Chassis M0 (EK1100)^PSL IO TCS Chassis M3 (EL3104); BoxAddr: 1032; Disabled: False
B978 = TerminalEL3104: EtherCAT Terminal EL3104 4-chn Analog Input; Rail: Middle; BoxNextB: TVEQGWSF; BoxPrev: SAGAPHCA; PortPrevFull: 1032/B; PortPrevShort: B; Fullname: TIID^Vertex PSL TCS (EtherCAT)^PSL IO TCS Chassis M0 (EK1100)^PSL IO TCS Chassis M5 (EL3104); BoxAddr: 1033; Disabled: False
B979 = TerminalEL3104: EtherCAT Terminal EL3104 4-chn Analog Input; Rail: Middle; BoxNextB: HNRNGGUO; BoxPrev: OURCQTCG; PortPrevFull: 1033/B; PortPrevShort: B; Fullname: TIID^Vertex PSL TCS (EtherCAT)^PSL IO TCS Chassis M0 (EK1100)^PSL IO TCS Chassis M6 (EL3104); BoxAddr: 1034; Disabled: False
B980 = TerminalEL3104: EtherCAT Terminal EL3104 4-chn Analog Input; Rail: Middle; BoxNextB: YITUYUQG; BoxPrev: TVEQGWSF; PortPrevFull: 1034/B; PortPrevShort: B; Fullname: TIID^Vertex PSL TCS (EtherCAT)^PSL IO TCS Chassis M0 (EK1100)^PSL IO TCS Chassis M7 (EL3104); BoxAddr: 1035; Disabled: False
B981 = TerminalEL9410: EtherCAT Terminal EL9410 Power; Rail: Right; BoxNextB: ECELEINR; BoxPrev: UJFOJQPA; PortPrevFull: 1022/B; PortPrevShort: B; Fullname: TIID^Vertex PSL TCS (EtherCAT)^PSL IO TCS Chassis R0 (EK1101)^PSL IO TCS Chassis R17 (EL9410); BoxAddr: 1023; Disabled: False
B982 = TerminalEL3104: EtherCAT Terminal EL3104 4-chn Analog Input; Rail: Right; BoxNextB: LKMTXVAQ; BoxPrev: FDMBFDOD; PortPrevFull: 1023/B; PortPrevShort: B; Fullname: TIID^Vertex PSL TCS (EtherCAT)^PSL IO TCS Chassis R0 (EK1101)^PSL IO TCS Chassis R18 (EL3104); BoxAddr: 1024; Disabled: False
B983 = TerminalEL3104: EtherCAT Terminal EL3104 4-chn Analog Input; Rail: Right; BoxNextB: OOOJPDKE; BoxPrev: ECELEINR; PortPrevFull: 1024/B; PortPrevShort: B; Fullname: TIID^Vertex PSL TCS (EtherCAT)^PSL IO TCS Chassis R0 (EK1101)^PSL IO TCS Chassis R19 (EL3104); BoxAddr: 1025; Disabled: False
B984 = TerminalEL3692-1chn: EtherCAT Terminal EL3692 1-chn Resistance Measurement; Rail: Right; BoxNextB: NDPTGJQU; BoxPrev: LKMTXVAQ; PortPrevFull: 1025/B; PortPrevShort: B; Fullname: TIID^Vertex PSL TCS (EtherCAT)^PSL IO TCS Chassis R0 (EK1101)^PSL IO TCS Chassis R20 (EL3692); BoxAddr: 1026; PDO Inputs: 0x1A00,0x1A02; PDO Outputs: 0x1600; Disabled: False
B985 = TerminalEL3692-1chn: EtherCAT Terminal EL3692 1-chn Resistance Measurement; Rail: Right; BoxNextB: PTCMURLN; BoxPrev: OOOJPDKE; PortPrevFull: 1026/B; PortPrevShort: B; Fullname: TIID^Vertex PSL TCS (EtherCAT)^PSL IO TCS Chassis R0 (EK1101)^PSL IO TCS Chassis R21 (EL3692); BoxAddr: 1027; PDO Inputs: 0x1A00,0x1A02; PDO Outputs: 0x1600; Disabled: False
B986 = TerminalEL4132: EtherCAT Terminal EL4132 2-chn Analog Ouput; Rail: Right; BoxNextB: XINAMSPO; BoxPrev: NDPTGJQU; PortPrevFull: 1027/B; PortPrevShort: B; Fullname: TIID^Vertex PSL TCS (EtherCAT)^PSL IO TCS Chassis R0 (EK1101)^PSL IO TCS Chassis R22 (EL4132); BoxAddr: 1028; Disabled: False
B987 = TerminalEL9011: EtherCAT Terminal EL9011 End; BoxType: TerminalPassive; Rail: Right; BoxPrev: PTCMURLN; PortPrevShort: B; Fullname: TIID^Vertex PSL TCS (EtherCAT)^PSL IO TCS Chassis R0 (EK1101)^PSL IO TCS Chassis R23 (EL9011); Disabled: False
B988 = TerminalEL9011: EtherCAT Terminal EL9011 End; BoxType: TerminalPassive; Rail: Middle; BoxPrev: HNRNGGUO; PortPrevShort: B; Fullname: TIID^Vertex PSL TCS (EtherCAT)^PSL IO TCS Chassis M0 (EK1100)^PSL IO TCS Chassis M8 (EL9011); Disabled: False
B989 = TerminalEL9190: EtherCAT Terminal EL9190 Supply; BoxType: TerminalPassive; Rail: Middle; BoxNextB: OURCQTCG; BoxPrev: XAYIQLOT; PortPrevShort: B; Fullname: TIID^Vertex PSL TCS (EtherCAT)^PSL IO TCS Chassis M0 (EK1100)^PSL IO TCS Chassis M4 (EL9190); Disabled: False
V423 V801 = RotationStage_RotationStageInStruct: RotationStageInStruct; BoxType: Variable; Instance: H1AuxCorner Instance; PLC: H1AuxCorner; Task: AuxCStd
V425 V427 = RotationStage_RotationStageInStruct: RotationStageInStruct; BoxType: Variable; Instance: H1TcsCorner Instance; PLC: H1TcsCorner; Task: TcsCStd
V508 = PSLEnv_PSLEnvInStruct: PSLEnvInStruct; BoxType: Variable; Instance: H1AuxCorner Instance; PLC: H1AuxCorner; Task: AuxCStd
V509 V510 = PZTMirror_PZTMirrorInStruct: PZTMirrorInStruct; BoxType: Variable; Instance: H1IscCorner Instance; PLC: H1IscCorner; Task: IscCStd
V511 = VariableOutBOOL: BOOL; Instance: H1AuxCorner Instance; PLC: H1AuxCorner; Task: AuxCStd
V512 = VariableOutBOOL: BOOL; Instance: H1TcsCorner Instance; PLC: H1TcsCorner; Task: TcsCStd
V513 = Picomotor_PicomotorFastInStruct: PicomotorFastInStruct; BoxType: Variable; Instance: H1AuxCorner Instance; PLC: H1AuxCorner; Task: AuxCFast
V514 = Picomotor_PicomotorOutStruct: PicomotorOutStruct; BoxType: Variable; Instance: H1AuxCorner Instance; PLC: H1AuxCorner; Task: AuxCStd
V515 = Picomotor_PicomotorFastOutStruct: PicomotorFastOutStruct; BoxType: Variable; Instance: H1AuxCorner Instance; PLC: H1AuxCorner; Task: AuxCFast
V516 V802 = RotationStage_RotationStageOutStruct: RotationStageOutStruct; BoxType: Variable; Instance: H1AuxCorner Instance; PLC: H1AuxCorner; Task: AuxCStd
V517 V518 = RotationStage_RotationStageOutStruct: RotationStageOutStruct; BoxType: Variable; Instance: H1TcsCorner Instance; PLC: H1TcsCorner; Task: TcsCStd
V699 = Picomotor_PicomotorInStruct: PicomotorInStruct; BoxType: Variable; Instance: H1AuxCorner Instance; PLC: H1AuxCorner; Task: AuxCStd
V803 V805 V807 V809 = TECController_ThermistorInStruct: ThermistorInStruct; BoxType: Variable; Instance: H1TcsCorner Instance; PLC: H1TcsCorner; Task: TcsCStd
V804 V806 V808 V810 = TECController_ThermistorOutStruct: ThermistorOutStruct; BoxType: Variable; Instance: H1TcsCorner Instance; PLC: H1TcsCorner; Task: TcsCStd
V811 V812 = ArrayAggregatorOut: Array [1..2] Of ThermistorOutStruct; Instance: H1TcsCorner Instance; PLC: H1TcsCorner; Task: TcsCStd; Lower Bound: 1; Upper Bound: 2
V813 V814 = ArrayAggregatorIn: Array [1..2] Of ThermistorInStruct; Instance: H1TcsCorner Instance; PLC: H1TcsCorner; Task: TcsCStd; Lower Bound: 1; Upper Bound: 2
V815 V816 = AWC_TSamsInStruct: TSamsInStruct; BoxType: Variable; Instance: H1TcsCorner Instance; PLC: H1TcsCorner; Task: TcsCStd
V817 V818 = AWC_TSamsOutStruct: TSamsOutStruct; BoxType: Variable; Instance: H1TcsCorner Instance; PLC: H1TcsCorner; Task: TcsCStd
V819 V821 V823 V825 V831 V833 V835 V837 = AWC_PSamsInStruct: PSamsInStruct; BoxType: Variable; Instance: H1TcsCorner Instance; PLC: H1TcsCorner; Task: TcsCStd
V820 V822 V824 V826 V832 V834 V836 V838 = AWC_PSamsFastInStruct: PSamsFastInStruct; BoxType: Variable; Instance: H1TcsCorner Instance; PLC: H1TcsCorner; Task: TcsCFast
